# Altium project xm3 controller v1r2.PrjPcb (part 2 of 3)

## Sheet LAUNCHPAD.SchDoc: Controller
size 492 x 365 mm; OrgAddr3: USA; Page Create Date: March  8, 1995; OrgName: Wolfspeed; OrgAddr1: 535 W Research Center Blvd.; Page Number: 1; Page Size: A; Comment: DualBrandTitleBlock1; Page Count: 8; OrgAddr2: Fayetteville, AR, 72701; Page Name: LAUNCHPAD; RevCode: V1.2; DsnPath: C:\Users\cnew\Downloads\xm3 controller v1r2-2022-03-14T15-49\xm3 controller v1r2.dsn; SchematicName: SCHEMATIC1; PageName: LAUNCHPAD; PageSize: A; TopSchematic: True
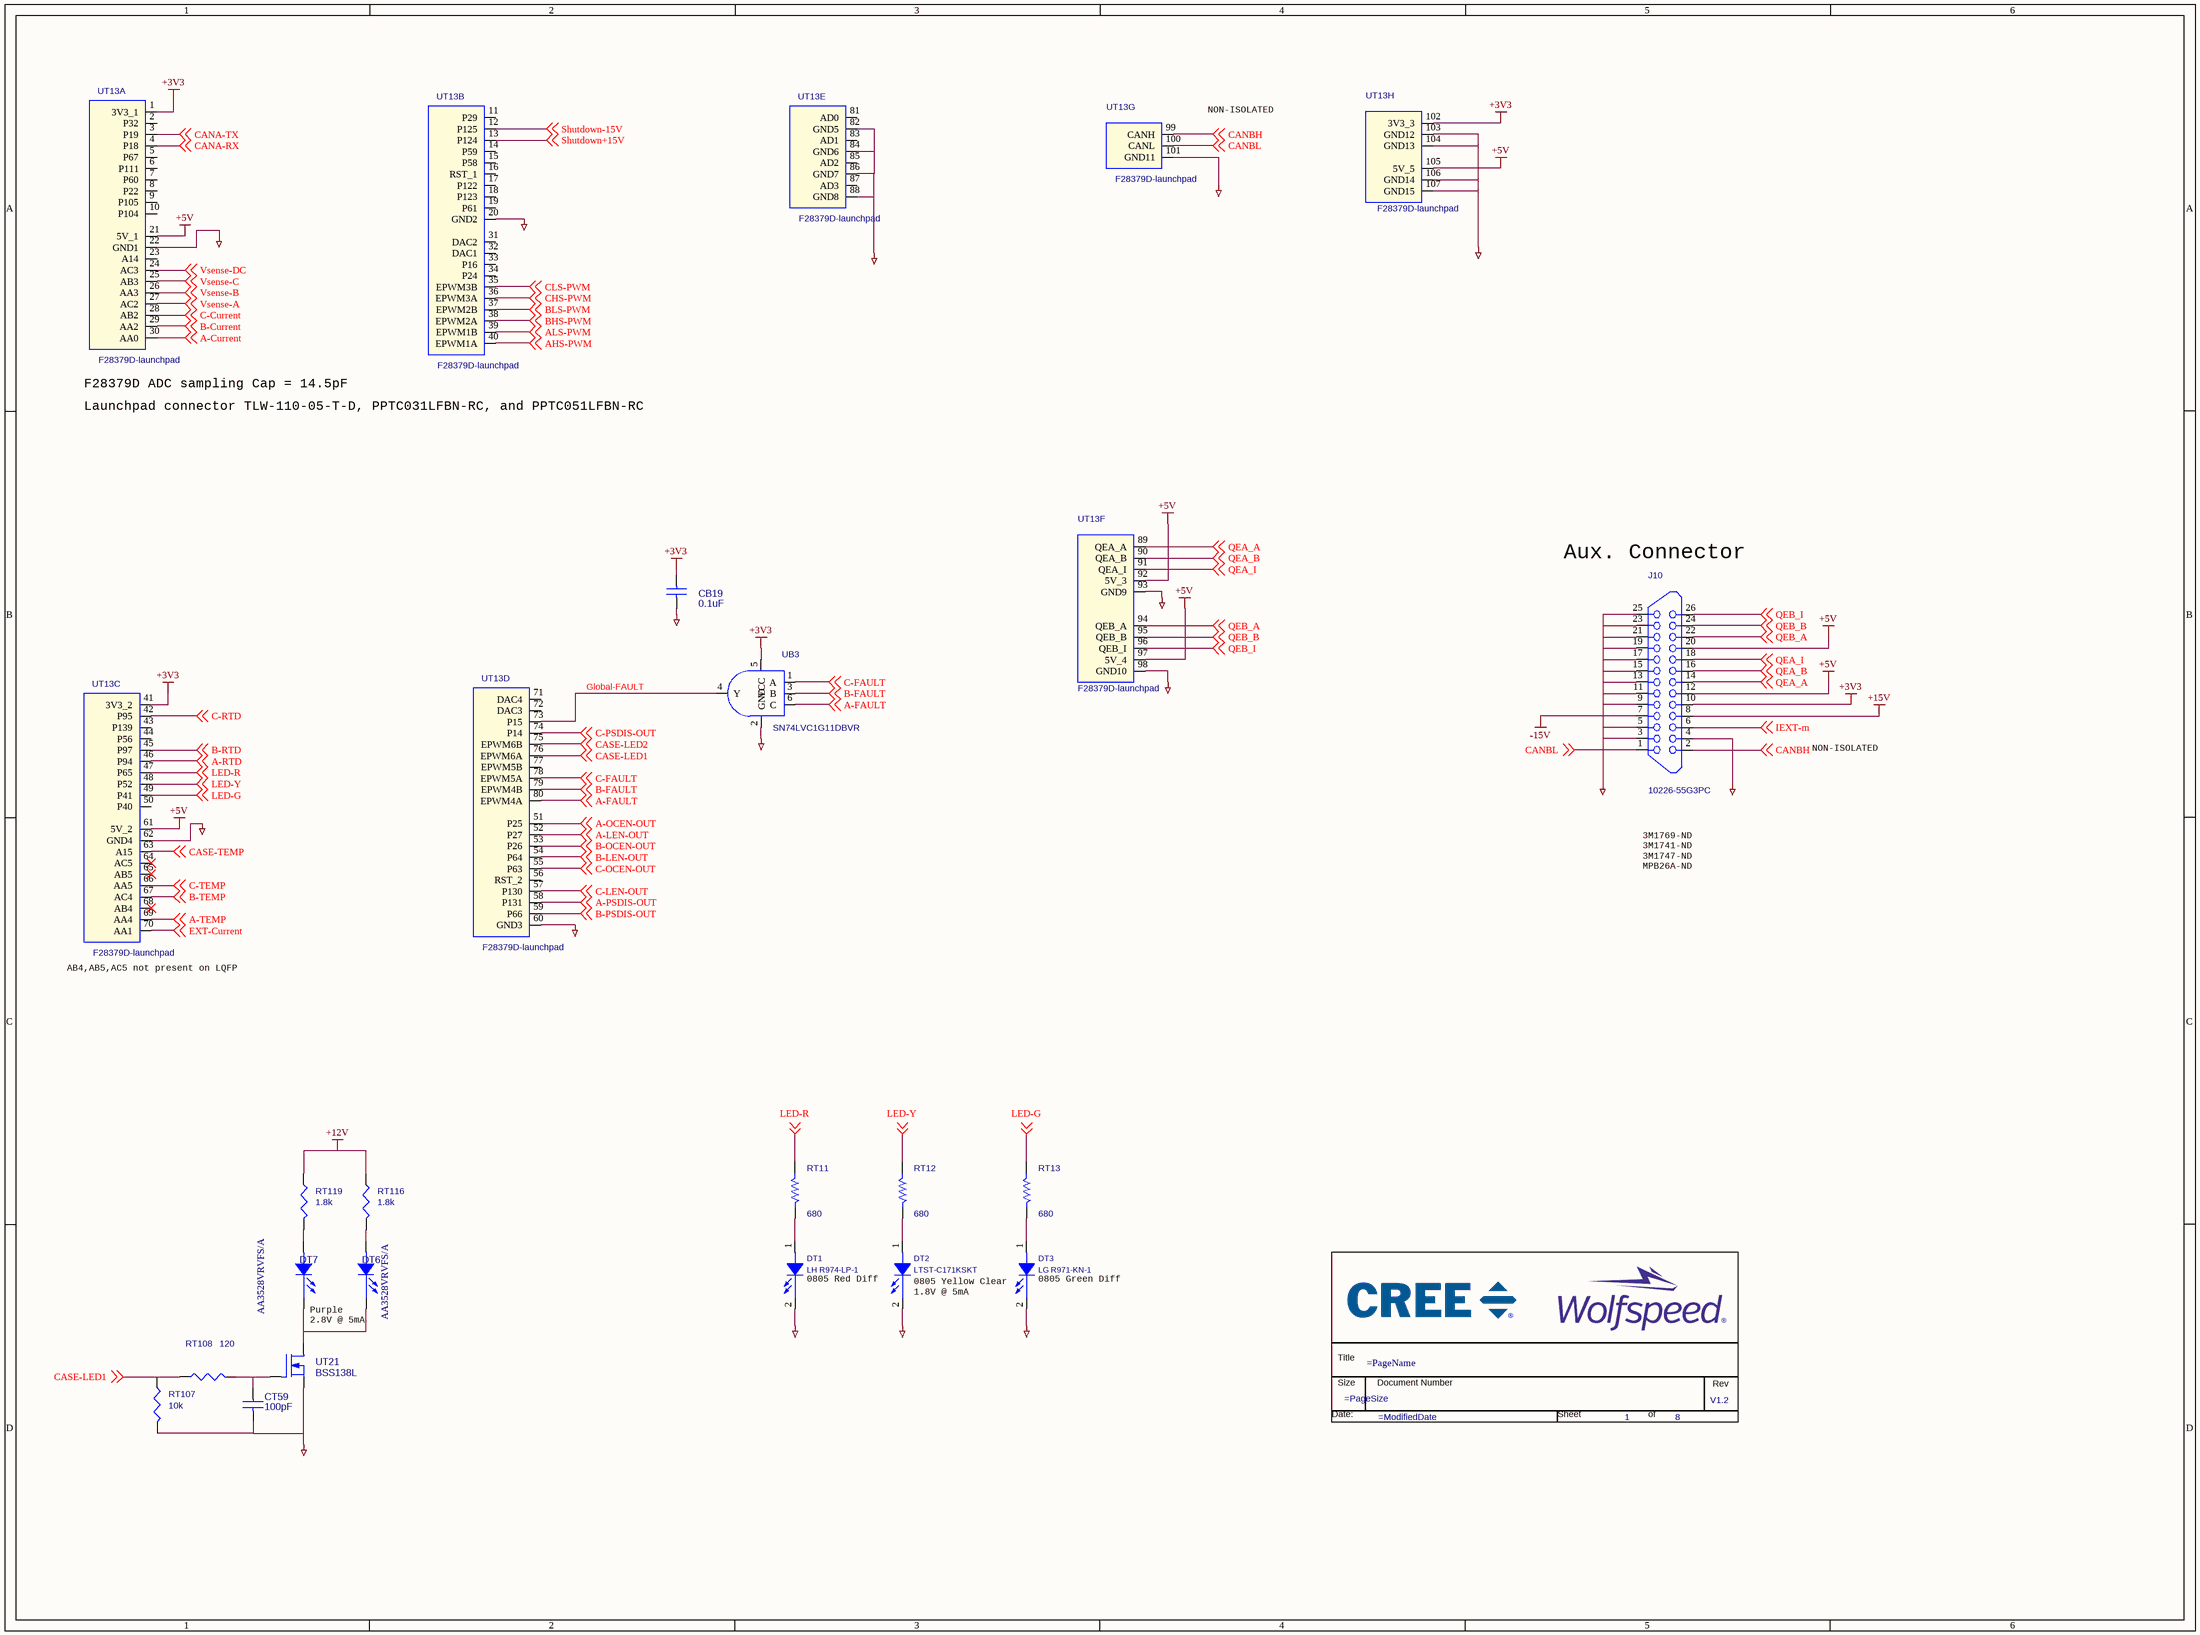
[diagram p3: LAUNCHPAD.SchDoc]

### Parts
(Parts that share a designator on the sheet are numbered #1, #2 ... from top to bottom, then left to right.)
*#4  Page Count: 8  Page Number: 1  RevCode: V1.2  (hidden comment: DualBrandTitleBlock1)  (graphical)
CB19  0.1uF  [CAPC1608X87N]
CT59  100pF  [CAPC1608X90N]
DT1  LH R974-LP-1  [D_0805]
DT2  LTST-C171KSKT  [D_0805]
DT3  LG R971-KN-1  [D_0805]
DT6  AA3528VRVFS/A  [D_1409]
DT7  AA3528VRVFS/A  [D_1409]
J10  10226-55G3PC  [MDR-26]
RT11  680  [RESC1608X55N]
RT12  680  [RESC1608X55N]
RT13  680  [RESC1608X55N]
RT107  10k  [RESC1608X65N]
RT108  120  [RESC1608X55N]
RT116  1.8k  [RESC2013X65N]
RT119  1.8k  [RESC2013X65N]
UB3  SN74LVC1G11DBVR  [SOT-23-6]
UT13  F28379D-launchpad  [F28379D-Launchpad-1]  (parts A,B,C,D,E,F,G,H of 8)
UT21  BSS138L  [SOT_23_3]

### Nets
0: CB19.2 CT59.2 DT1.2(C) DT2.2(C) DT3.2(C) J10.3 J10.4 J10.5 J10.9 J10.11 J10.13 J10.15 J10.17 J10.19 J10.21 J10.23 J10.25 RT107.2 UB3.2(GND) UT13.20(GND2) UT13.22(GND1) UT13.60(GND3) UT13.62(GND4) UT13.82(GND5) UT13.84(GND6) UT13.86(GND7) UT13.88(GND8) UT13.93(GND9) UT13.98(GND10) UT13.101(GND11) UT13.103(GND12) UT13.104(GND13) UT13.106(GND14) UT13.107(GND15) UT21.2(S)
+3V3: CB19.1 J10.10 UB3.5(VCC) UT13.1(3V3_1) UT13.41(3V3_2) UT13.102(3V3_3)
+5V: J10.12 J10.20 UT13.21(5V_1) UT13.61(5V_2) UT13.92(5V_3) UT13.97(5V_4) UT13.105(5V_5)
+12V: RT116.1 RT119.1
+15V: J10.8
-15V: J10.7
A-Current: UT13.30(AA0) ; off-sheet A-Current
A-FAULT: UB3.6(C) UT13.80(EPWM4A) ; off-sheet A-FAULT
A-LEN-OUT: UT13.52(P27) ; off-sheet A-LEN-OUT
A-OCEN-OUT: UT13.51(P25) ; off-sheet A-OCEN-OUT
A-PSDIS-OUT: UT13.58(P131) ; off-sheet A-PSDIS-OUT
A-RTD: UT13.46(P94) ; off-sheet A-RTD
A-TEMP: UT13.69(AA4) ; off-sheet A-TEMP
AHS-PWM: UT13.40(EPWM1A) ; off-sheet AHS-PWM
ALS-PWM: UT13.39(EPWM1B) ; off-sheet ALS-PWM
B-Current: UT13.29(AA2) ; off-sheet B-Current
B-FAULT: UB3.3(B) UT13.79(EPWM4B) ; off-sheet B-FAULT
B-LEN-OUT: UT13.54(P64) ; off-sheet B-LEN-OUT
B-OCEN-OUT: UT13.53(P26) ; off-sheet B-OCEN-OUT
B-PSDIS-OUT: UT13.59(P66) ; off-sheet B-PSDIS-OUT
B-RTD: UT13.45(P97) ; off-sheet B-RTD
B-TEMP: UT13.67(AC4) ; off-sheet B-TEMP
BHS-PWM: UT13.38(EPWM2A) ; off-sheet BHS-PWM
BLS-PWM: UT13.37(EPWM2B) ; off-sheet BLS-PWM
C-Current: UT13.28(AB2) ; off-sheet C-Current
C-FAULT: UB3.1(A) UT13.78(EPWM5A) ; off-sheet C-FAULT
C-LEN-OUT: UT13.57(P130) ; off-sheet C-LEN-OUT
C-OCEN-OUT: UT13.55(P63) ; off-sheet C-OCEN-OUT
C-PSDIS-OUT: UT13.74(P14) ; off-sheet C-PSDIS-OUT
C-RTD: UT13.42(P95) ; off-sheet C-RTD
C-TEMP: UT13.66(AA5) ; off-sheet C-TEMP
CANA-RX: UT13.4(P18) ; off-sheet CANA-RX
CANA-TX: UT13.3(P19) ; off-sheet CANA-TX
CANBH: J10.2 UT13.99(CANH) ; off-sheet CANBH
CANBL: J10.1 UT13.100(CANL) ; off-sheet CANBL
CASE-LED1: RT107.1 RT108.1 UT13.76(EPWM6A) ; off-sheet CASE-LED1
CASE-LED2: UT13.75(EPWM6B) ; off-sheet CASE-LED2
CASE-TEMP: UT13.63(A15) ; off-sheet CASE-TEMP
CHS-PWM: UT13.36(EPWM3A) ; off-sheet CHS-PWM
CLS-PWM: UT13.35(EPWM3B) ; off-sheet CLS-PWM
EXT-Current: UT13.70(AA1) ; off-sheet EXT-Current
Global-FAULT: UB3.4(Y) UT13.73(P15)
IEXT-m: J10.6 ; off-sheet IEXT-m
LED-G: RT13.1 UT13.49(P41) ; off-sheet LED-G
LED-R: RT11.1 UT13.47(P65) ; off-sheet LED-R
LED-Y: RT12.1 UT13.48(P52) ; off-sheet LED-Y
QEA_A: J10.14 UT13.89(QEA_A) ; off-sheet QEA_A
QEA_B: J10.16 UT13.90(QEA_B) ; off-sheet QEA_B
QEA_I: J10.18 UT13.91(QEA_I) ; off-sheet QEA_I
QEB_A: J10.22 UT13.94(QEB_A) ; off-sheet QEB_A
QEB_B: J10.24 UT13.95(QEB_B) ; off-sheet QEB_B
QEB_I: J10.26 UT13.96(QEB_I) ; off-sheet QEB_I
Shutdown+15V: UT13.13(P124) ; off-sheet Shutdown+15V
Shutdown-15V: UT13.12(P125) ; off-sheet Shutdown-15V
Vsense-A: UT13.27(AC2) ; off-sheet Vsense-A
Vsense-B: UT13.26(AA3) ; off-sheet Vsense-B
Vsense-C: UT13.25(AB3) ; off-sheet Vsense-C
Vsense-DC: UT13.24(AC3) ; off-sheet Vsense-DC
NetCT59_1: CT59.1 RT108.2 UT21.1(G)
NetDT1_1: DT1.1(A) RT11.2
NetDT2_1: DT2.1(A) RT12.2
NetDT3_1: DT3.1(A) RT13.2
NetDT6_1: DT6.1(ANODE) RT116.2
NetDT6_2: DT6.2(CATHODE) DT7.2(CATHODE) UT21.3(D)
NetDT7_1: DT7.1(ANODE) RT119.2

Not connected (* = marked no-connect by the designer): UT13 2(P32) 5(P67) 6(P111) 7(P60) 8(P22) 9(P105) 10(P104) 11(P29) 14(P59) 15(P58) 16(RST_1) 17(P122) 18(P123) 19(P61) 23(A14) 31(DAC2) 32(DAC1) 33(P16) 34(P24) 43(P139) 44(P56) 50(P40) 56(RST_2) 64(AC5)* 65(AB5)* 68(AB4)* 71(DAC4) 72(DAC3) 77(EPWM5B) 81(AD0) 83(AD1) 85(AD2) 87(AD3)

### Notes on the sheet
- NON-ISOLATED
- (near UT13) F28379D ADC sampling Cap = 14.5pF
- Launchpad connector TLW-110-05-T-D, PPTC031LFBN-RC, and PPTC051LFBN-RC
- Aux. Connector
- 3M1769-ND
  3M1741-ND
  3M1747-ND
  MPB26A-ND
- (near UT13) AB4,AB5,AC5 not present on LQFP
- Purple
  2.8V @ 5mA
- (near DT1) 0805 Red Diff
- 0805 Yellow Clear
  1.8V @ 5mA
- (near DT3) 0805 Green Diff

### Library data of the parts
*#4 = DualBrandTitleBlock1: OrgAddr3: USA; OrgAddr2: Fayetteville, AR, 72701; OrgAddr1: 535 W Research Center Blvd.; OrgName: Wolfspeed; Title: Controller
CB19 = CAP: CAP CER 0.1UF 25V X7R 0603; Part Reference: CB19; PART_NUMBER: TMP-847; Manufacturer: Kemet; Manufacturer PN: C0603C104K3RACTU; Company Part Status: New; Dielectric Type: Capacitors; Tolerance: 10%; CLASS: DISCRETE
CT59 = CAP: CAP CER 100PF 50V 5% NP0 0603; Part Reference: CT59; Manufacturer PN: CL10C101JB8NNNC; Manufacturer: Samsung Electro-Mechanics America, Inc; PART_NUMBER: TMP-455; Company Part Status: New; CLASS: DISCRETE; Temperature Coefficient: C0G, NP0; Dielectric Type: Capacitors
DT1 = LED_0: LED RED DIFFUSED 0805 SMD; Part Reference: DT1; Company Part Status: New; PART_NUMBER: TMP-917; Manufacturer: OSRAM Opto Semiconductors Inc.; Rated Voltage: 1.8V @ 20mA; CLASS: DISCRETE
DT2 = LED_0: LED YELLOW CLEAR 0805 SMD; Part Reference: DT2; Company Part Status: New; Manufacturer: Lite-On Inc.; PART_NUMBER: TMP-656; CLASS: DISCRETE
DT3 = LED_0: LED GREEN DIFFUSED 0805 SMD; Part Reference: DT3; Manufacturer: OSRAM Opto Semiconductors Inc.; PART_NUMBER: TMP-915; Company Part Status: New; CLASS: DISCRETE; Rated Voltage: 2.2V
DT6 = LED - Purple: Standard LEDs - SMD Violet Water Clear 250mcd 120 Deg; Manufacturer: Kingbright; Part Reference: DT6; PART_NUMBER: TMP-147; Company Part Status: Released; CLASS: DISCRETE
DT7 = LED - Purple: Standard LEDs - SMD Violet Water Clear 250mcd 120 Deg; Manufacturer: Kingbright; Part Reference: DT7; PART_NUMBER: TMP-147; Company Part Status: Released; CLASS: DISCRETE
J10 = CONN CENT RCPT 26: CONN RCPT 26POS R/A SOLDER; Part Reference: J10; Manufacturer: 3M; Company Part Status: New; CLASS: IO
RT11 = RES_Dup1: RES SMD 680 OHM 1% 1/10W 0603; Part Reference: RT11; Company Part Status: New; Manufacturer: Yageo; Manufacturer PN: RC0603FR-07680RL; Temperature Coefficient: 100ppm/C; Rated Power: 0.1W, 1/10W; CLASS: DISCRETE
RT12 = RES_Dup1: RES SMD 680 OHM 1% 1/10W 0603; Part Reference: RT12; Manufacturer PN: RC0603FR-07680RL; Manufacturer: Yageo; Company Part Status: New; CLASS: DISCRETE; Rated Power: 0.1W, 1/10W; Temperature Coefficient: 100ppm/C
RT13 = RES_Dup1: RES SMD 680 OHM 1% 1/10W 0603; Part Reference: RT13; Manufacturer PN: RC0603FR-07680RL; Manufacturer: Yageo; Company Part Status: New; CLASS: DISCRETE; Rated Power: 0.1W, 1/10W; Temperature Coefficient: 100ppm/C
RT107 = R: RES SMD 10K OHM 1% 1/10W 0603; Part Reference: RT107; PART_NUMBER: TMP-380; Manufacturer: Rohm Semiconductor; Manufacturer PN: MCR03ERTF1002; Company Part Status: New; Temperature Coefficient: 100ppm/C; Rated Power: 0.1W, 1/10W; CLASS: DISCRETE
RT108 = R: RES SMD 120 OHM 5% 1/10W 0603; Part Reference: RT108; Manufacturer PN: RC0603JR-07120RL; Manufacturer: Yageo; PART_NUMBER: TMP-619; Company Part Status: New; CLASS: DISCRETE; Rated Power: 0.1W, 1/10W; Temperature Coefficient: 100ppm/C
RT116 = R: RES 1.8K OHM 1/8W 1% 0805 SMD; Part Reference: RT116; Manufacturer PN: KTR10EZPF1801; Manufacturer: Rohm Semiconductor; PART_NUMBER: TMP-277; CLASS: DISCRETE; Rated Power: 0.125W, 1/8W; Temperature Coefficient: 100ppm/C
RT119 = R: RES 1.8K OHM 1/8W 1% 0805 SMD; Part Reference: RT119; PART_NUMBER: TMP-277; Manufacturer: Rohm Semiconductor; Manufacturer PN: KTR10EZPF1801; Temperature Coefficient: 100ppm/C; Rated Power: 0.125W, 1/8W; CLASS: DISCRETE
UB3 = AND3_1X_6PIN: IC GATE AND 1CH 3-INP SOT23-6; Part Reference: UB3; Manufacturer: Texas Instruments; Company Part Status: New; Supply Voltage: 1.65 V - 5.5 V; PCB Footprint: SOT_23_6
UT13 = F28379D-launchpad: Part Reference: UT13
UT21 = MOSFET_N_GSD: MOSFET N-CH 50V 0.2A SOT-23; Part Reference: UT21; Manufacturer: ON Semiconductor; Company Part Status: Released; CLASS: DISCRETE; Polarity: N-Channel; Rated Power: 350mW

## Sheet Power Supply.SchDoc: Controller
size 492 x 365 mm; OrgAddr3: USA; Page Create Date: March  8, 1995; OrgName: Wolfspeed; OrgAddr1: 535 W Research Center Blvd.; Page Number: 6; Page Size: A; Comment: DualBrandTitleBlock1; Page Count: 8; OrgAddr2: Fayetteville, AR, 72701; Page Name: Power Supply; RevCode: V1.2; DsnPath: C:\Users\cnew\Downloads\xm3 controller v1r2-2022-03-14T15-49\xm3 controller v1r2.dsn; SchematicName: SCHEMATIC1; PageName: Power Supply; PageSize: A; TopSchematic: True
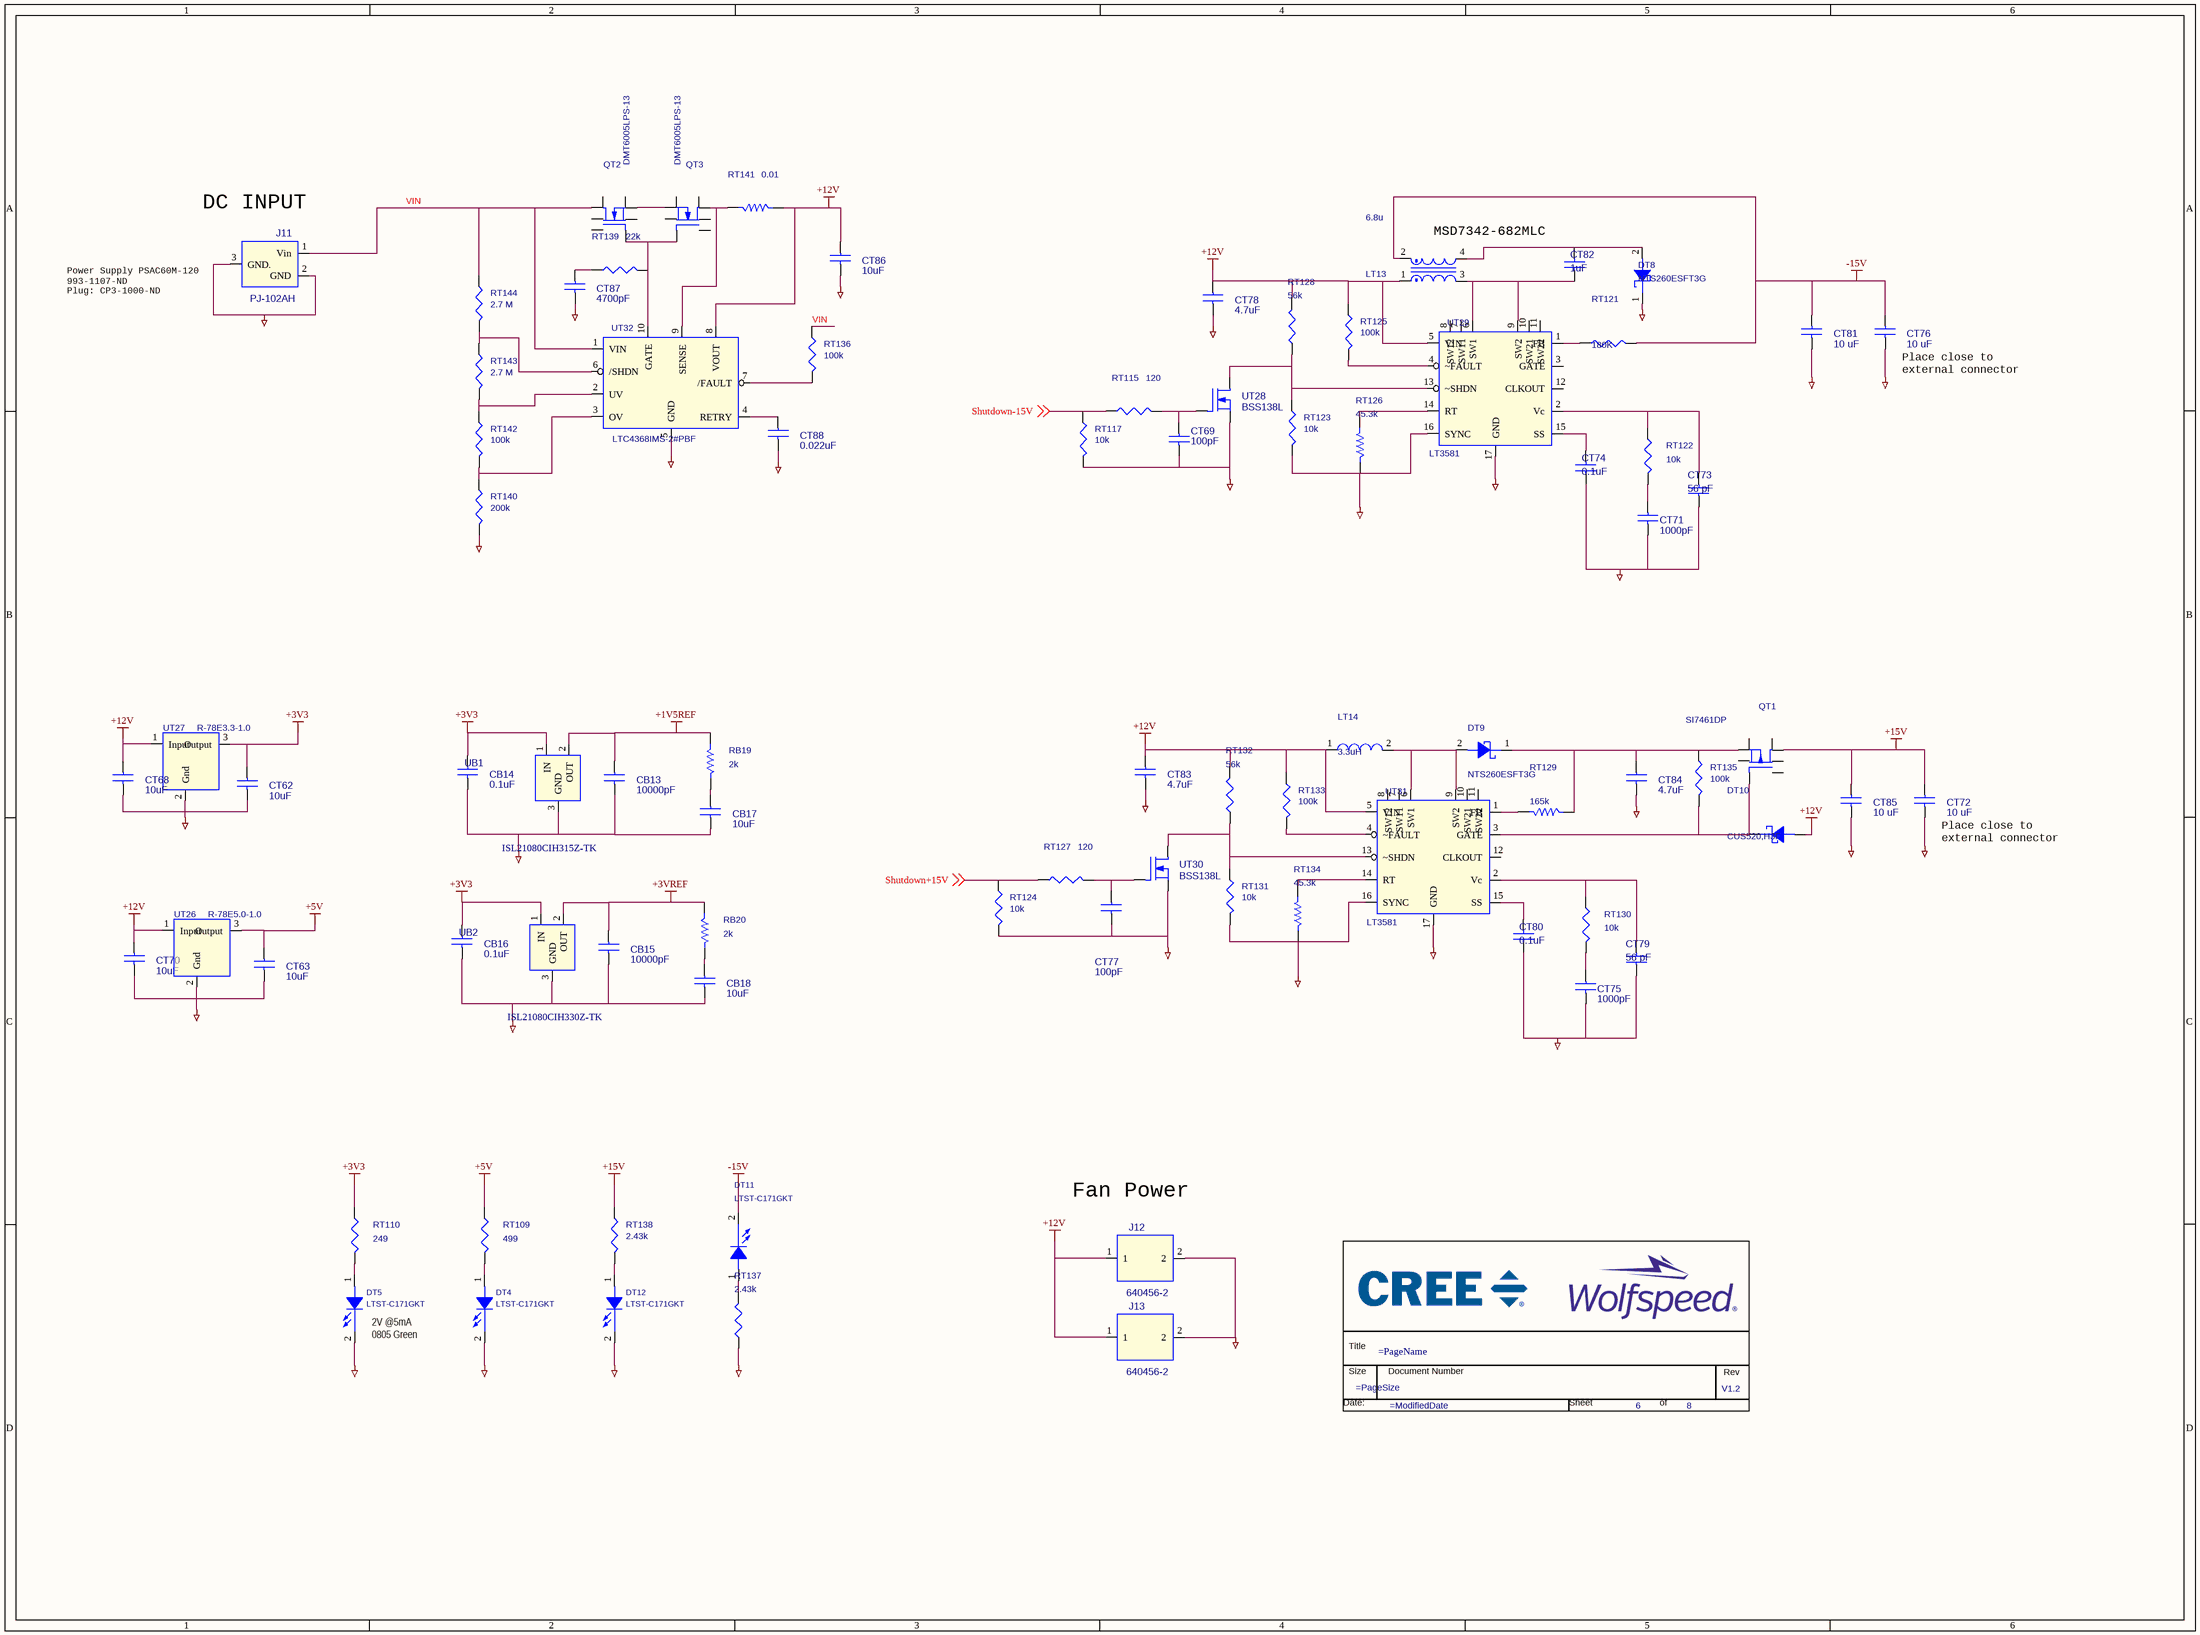
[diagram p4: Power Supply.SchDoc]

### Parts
(Parts that share a designator on the sheet are numbered #1, #2 ... from top to bottom, then left to right.)
*#5  Page Count: 8  Page Number: 6  RevCode: V1.2  (hidden comment: DualBrandTitleBlock1)  (graphical)
CB13  10000pF  [CAPC1608X90N]
CB14  0.1uF  [CAPC1608X87N]
CB15  10000pF  [CAPC1608X90N]
CB16  0.1uF  [CAPC1608X87N]
CB17  10uF  [CAPC1608X90N]
CB18  10uF  [CAPC1608X90N]
CT62  10uF  [CAPC2012X135N]
CT63  10uF  [CAPC2012X135N]
CT68  10uF  [CAPC2012X135N]
CT69  100pF  [CAPC1608X90N]
CT70  10uF  [CAPC2012X135N]
CT71  1000pF  [CAPC1608X90N]
CT72  10 uF  [CAPC3216X180N]
CT73  56 pF  [CAPC1608X90N]
CT74  0.1uF  [CAPC1608X90N]
CT75  1000pF  [CAPC1608X90N]
CT76  10 uF  [CAPC3216X180N]
CT77  100pF  [CAPC1608X90N]
CT78  4.7uF  [CAPc3216X180N]
CT79  56 pF  [CAPC1608X90N]
CT80  0.1uF  [CAPC1608X90N]
CT81  10 uF  [CAPC3216X180N]
CT82  1uF  [CAPC2012X70N]
CT83  4.7uF  [CAPc3216X180N]
CT84  4.7uF  [CAPc3216X180N]
CT85  10 uF  [CAPC3216X180N]
CT86  10uF  [CAPC2012X135N]
CT87  4700pF  [CAPC1608X90N]
CT88  0.022uF  [CAPC2012X70N]
DT4  LTST-C171GKT  [D_0805]
DT5  LTST-C171GKT  [D_0805]
DT8  NTS260ESFT3G  [SOD-123F-AC]
DT9  NTS260ESFT3G  [SOD-123F-AC]
DT10  CUS520,H3F  [SOD-323-AC]
DT11  LTST-C171GKT  [D_0805]
DT12  LTST-C171GKT  [D_0805]
J11  PJ-102AH  [powerjack]
J12  640456-2  [CON_1x2_vert_lock]
J13  640456-2  [CON_1x2_vert_lock]
LT13  6.8u  [SRF1260]
LT14  3.3uH  [IND-5040]
QT1  SI7461DP  [POWER-SO8]
QT2  DMT6005LPS-13  [POWER-SO8]
QT3  DMT6005LPS-13  [POWER-SO8]
RB19  2k  [RESC1608X55N]
RB20  2k  [RESC1608X55N]
RT109  499  [RESC2012X60N]
RT110  249  [RESC2012X60N]
RT115  120  [RESC1608X55N]
RT117  10k  [RESC1608X65N]
RT121  180K  [RESC1608X55N]
RT122  10k  [RESC1608X65N]
RT123  10k  [RESC1608X65N]
RT124  10k  [RESC1608X65N]
RT125  100k  [RESC1608X55N]
RT126  45.3k  [RESC1608X55N]
RT127  120  [RESC1608X55N]
RT128  56k  [RESC1608X55N]
RT129  165k  [RESC1608X55N]
RT130  10k  [RESC1608X65N]
RT131  10k  [RESC1608X65N]
RT132  56k  [RESC1608X55N]
RT133  100k  [RESC1608X55N]
RT134  45.3k  [RESC1608X55N]
RT135  100k  [RESC1608X55N]
RT136  100k  [RESC1608X55N]
RT137  2.43k  [RESC2012X60N]
RT138  2.43k  [RESC2012X60N]
RT139  22k  [RESC1608X55N]
RT140  200k  [RESC1608X55N]
RT141  0.01  [RESC6432X70N]
RT142  100k  [RESC1608X55N]
RT143  2.7 M  [RESC1608X55N]
RT144  2.7 M  [RESC1608X55N]
UB1  ISL21080CIH315Z-TK  [SOT_23_3]
UB2  ISL21080CIH330Z-TK  [SOT_23_3]
UT26  R-78E5.0-1.0  [TO_220_3]
UT27  R-78E3.3-1.0  [TO_220_3]
UT28  BSS138L  [SOT_23_3]
UT29  LT3581  [MSOP-16-EP]
UT30  BSS138L  [SOT_23_3]
UT31  LT3581  [MSOP-16-EP]
UT32  LTC4368IMS-2#PBF  [MSOP_10]

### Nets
0: CB13.2 CB14.2 CB15.2 CB16.2 CB17.2 CB18.2 CT62.2 CT63.2 CT68.2 CT69.2 CT70.2 CT71.2 CT72.2 CT73.1 CT74.1 CT75.2 CT76.2 CT77.2 CT78.2 CT79.1 CT80.1 CT81.2 CT83.2 CT84.2 CT85.2 CT86.2 CT87.2 CT88.2 DT4.2(C) DT5.2(C) DT8.1(C) DT12.2(C) J11.2(GND) J11.3(GND.) J12.2 J13.2 RT117.2 RT123.2 RT124.2 RT126.1 RT131.2 RT134.1 RT137.1 RT140.2 UB1.3(GND) UB2.3(GND) UT26.2(Gnd) UT27.2(Gnd) UT28.2(S) UT29.16(SYNC) UT29.17(GND) UT30.2(S) UT31.16(SYNC) UT31.17(GND) UT32.5(GND)
+1V5REF: CB13.1 RB19.1 UB1.2(OUT)
+3V3: CB14.1 CB16.1 CT62.1 RT110.1 UB1.1(IN) UB2.1(IN) UT27.3(Output)
+3VREF: CB15.1 RB20.1 UB2.2(OUT)
+5V: CT63.1 RT109.1 UT26.3(Output)
+12V: CT68.1 CT70.1 CT78.1 CT83.1 CT86.1 DT10.A(ANODE) J12.1 J13.1 LT13.1 LT14.1 RT125.1 RT128.2 RT132.2 RT133.1 RT141.2 UT26.1(Input) UT27.1(Input) UT29.5(VIN) UT31.5(VIN) UT32.8(VOUT)
+15V: CT72.1 CT85.1 QT1.5(D) RT138.1
-15V: CT76.1 CT81.1 DT11.2(C) LT13.2 RT121.2
Shutdown+15V: RT124.1 RT127.1 ; off-sheet Shutdown+15V
Shutdown-15V: RT115.1 RT117.1 ; off-sheet Shutdown-15V
VIN: J11.1(Vin) QT2.5(D) RT136.1 RT144.1 UT32.1(VIN)
NetCB17_1: CB17.1 RB19.2
NetCB18_1: CB18.1 RB20.2
NetCT69_1: CT69.1 RT115.2 UT28.1(G)
NetCT71_1: CT71.1 RT122.2
NetCT73_2: CT73.2 RT122.1 UT29.2(Vc)
NetCT74_2: CT74.2 UT29.15(SS)
NetCT75_1: CT75.1 RT130.2
NetCT77_1: CT77.1 RT127.2 UT30.1(G)
NetCT79_2: CT79.2 RT130.1 UT31.2(Vc)
NetCT80_2: CT80.2 UT31.15(SS)
NetCT82_1: CT82.1 LT13.3 UT29.6(SW1) UT29.9(SW2)
NetCT82_2: CT82.2 DT8.2(A) LT13.4
NetCT84_1: CT84.1 DT9.1(C) QT1.1(S) RT129.2 RT135.1
NetCT87_1: CT87.1 RT139.1
NetCT88_1: CT88.1 UT32.4(RETRY)
NetDT4_1: DT4.1(A) RT109.2
NetDT5_1: DT5.1(A) RT110.2
NetDT9_2: DT9.2(A) LT14.2 UT31.6(SW1) UT31.9(SW2)
NetDT10_C: DT10.C(CATHODE) QT1.4(G) RT135.2 UT31.3(GATE)
NetDT11_1: DT11.1(A) RT137.2
NetDT12_1: DT12.1(A) RT138.2
NetQT2_1: QT2.1(S) QT3.1(S)
NetQT2_4: QT2.4(G) QT3.4(G) RT139.2 UT32.10(GATE)
NetQT3_5: QT3.5(D) RT141.1 UT32.9(SENSE)
NetRT121_1: RT121.1 UT29.1(FB)
NetRT123_1: RT123.1 RT128.1 UT28.3(D) UT29.13(~SHDN)
NetRT125_2: RT125.2 UT29.4(~FAULT)
NetRT126_2: RT126.2 UT29.14(RT)
NetRT129_1: RT129.1 UT31.1(FB)
NetRT131_1: RT131.1 RT132.1 UT30.3(D) UT31.13(~SHDN)
NetRT133_2: RT133.2 UT31.4(~FAULT)
NetRT134_2: RT134.2 UT31.14(RT)
NetRT136_2: RT136.2 UT32.7(/FAULT)
NetRT140_1: RT140.1 RT142.2 UT32.3(OV)
NetRT142_1: RT142.1 RT143.2 UT32.2(UV)
NetRT143_1: RT143.1 RT144.2 UT32.6(/SHDN)

Not connected (* = marked no-connect by the designer): QT1 2(S1) 3(S2) 6(D1) 7(D2) 8(D3); QT2 2(S1) 3(S2) 6(D1) 7(D2) 8(D3); QT3 2(S1) 3(S2) 6(D1) 7(D2) 8(D3); UT29 3(GATE) 7(SW11) 8(SW12) 10(SW21) 11(SW22) 12(CLKOUT); UT31 7(SW11) 8(SW12) 10(SW21) 11(SW22) 12(CLKOUT)

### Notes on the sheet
- (near J11) DC INPUT
- (near LT13) MSD7342-682MLC
- (near J11) Power Supply PSAC60M-120
  993-1107-ND
- Plug: CP3-1000-ND
- (near CT76) Place close to
  external connector
- (near CT72) Place close to
  external connector
- Fan Power
- (near DT5) 2V @5mA
  0805 Green

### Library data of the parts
*#5 = DualBrandTitleBlock1: as *#4 on sheet LAUNCHPAD
CB13 = CAP: CAP CER 10000PF 25V 10% X7R 0603; Part Reference: CB13; PART_NUMBER: TMP-566; Manufacturer: Samsung Electro-Mechanics America, Inc.; Manufacturer PN: CL10B103KA8NNNC; Company Part Status: New; Dielectric Type: Capacitors; CLASS: DISCRETE
CB14 = CAP: CAP CER 0.1UF 25V X7R 0603; Part Reference: CB14; PART_NUMBER: TMP-847; Manufacturer: Kemet; Manufacturer PN: C0603C104K3RACTU; Company Part Status: New; Dielectric Type: Capacitors; Tolerance: 10%; CLASS: DISCRETE
CB15 = CAP: CAP CER 10000PF 25V 10% X7R 0603; Part Reference: CB15; PART_NUMBER: TMP-566; Manufacturer: Samsung Electro-Mechanics America, Inc.; Manufacturer PN: CL10B103KA8NNNC; Company Part Status: New; Dielectric Type: Capacitors; CLASS: DISCRETE
CB16 = CAP: CAP CER 0.1UF 25V X7R 0603; Part Reference: CB16; PART_NUMBER: TMP-847; Manufacturer: Kemet; Manufacturer PN: C0603C104K3RACTU; Company Part Status: New; Dielectric Type: Capacitors; Tolerance: 10%; CLASS: DISCRETE
CB17 = CAP: CAP CER 10UF 6.3V X7R 0603; Part Reference: CB17; Manufacturer: Samsung Electro-Mechanics America, Inc.; Manufacturer PN: CL10B106MQ8NRNC; Company Part Status: New; Dielectric Type: Capacitors; Tolerance: 20%; CLASS: DISCRETE
CB18 = CAP: CAP CER 10UF 6.3V X7R 0603; Part Reference: CB18; Manufacturer: Samsung Electro-Mechanics America, Inc.; Manufacturer PN: CL10B106MQ8NRNC; Company Part Status: New; Dielectric Type: Capacitors; Tolerance: 20%; CLASS: DISCRETE
CT62 = CAP: CAP CER 10UF 25V X7S 0805; Part Reference: CT62; Manufacturer: Murata Electronics North America; Manufacturer PN: GRM21BC71E106KE11L; Company Part Status: New; Dielectric Type: Capacitors; Tolerance: 10%; CLASS: DISCRETE
CT63 = CAP: CAP CER 10UF 25V X7S 0805; Part Reference: CT63; Manufacturer: Murata Electronics North America; Manufacturer PN: GRM21BC71E106KE11L; Company Part Status: New; Dielectric Type: Capacitors; Tolerance: 10%; CLASS: DISCRETE
CT68 = CAP: CAP CER 10UF 25V X7S 0805; Part Reference: CT68; Manufacturer: Murata Electronics North America; Manufacturer PN: GRM21BC71E106KE11L; Company Part Status: New; Dielectric Type: Capacitors; Tolerance: 10%; CLASS: DISCRETE
CT69 = CAP: CAP CER 100PF 50V 5% NP0 0603; Part Reference: CT69; PART_NUMBER: TMP-455; Manufacturer: Samsung Electro-Mechanics America, Inc; Manufacturer PN: CL10C101JB8NNNC; Company Part Status: New; Dielectric Type: Capacitors; Temperature Coefficient: C0G, NP0; CLASS: DISCRETE
CT70 = CAP: CAP CER 10UF 25V X7S 0805; Part Reference: CT70; Manufacturer: Murata Electronics North America; Manufacturer PN: GRM21BC71E106KE11L; Company Part Status: New; Dielectric Type: Capacitors; Tolerance: 10%; CLASS: DISCRETE
CT71 = CAP: CAP CER 1000PF 50V X7R 0603; Part Reference: CT71; PART_NUMBER: TMP-887; Manufacturer: TDK Corporation; Manufacturer PN: CGA3E2X7R1H102K080AA; Dielectric Type: Capacitors; Tolerance: 10%; CLASS: DISCRETE
CT72 = CAP: CAP CER 10UF 25V X7R 1206; Part Reference: CT72; Manufacturer PN: CL31B106KAHNNNE; Manufacturer: Samsung Electro-Mechanics; Company Part Status: Released; CLASS: DISCRETE; Tolerance: 10%; Dielectric Type: Capacitors
CT73 = CAP: CAP CER 56PF 50V C0G/NP0 0603; Part Reference: CT73; Manufacturer: Samsung Electro-Mechanics; Manufacturer PN: CL10C560JB8NNNC; Company Part Status: Released; Dielectric Type: Capacitors; Temperature Coefficient: C0G, NP0; Tolerance: 5%; CLASS: DISCRETE
CT74 = CAP: CAP CER 0.1UF 50V X7R 0603; Part Reference: CT74; Manufacturer PN: CC0603KRX7R9BB104; Manufacturer: Yageo; Company Part Status: Released; CLASS: DISCRETE; Tolerance: 10%; Dielectric Type: Capacitors
CT75 = CAP: CAP CER 1000PF 50V X7R 0603; Part Reference: CT75; PART_NUMBER: TMP-887; Manufacturer: TDK Corporation; Manufacturer PN: CGA3E2X7R1H102K080AA; Dielectric Type: Capacitors; Tolerance: 10%; CLASS: DISCRETE
CT76 = CAP: CAP CER 10UF 25V X7R 1206; Part Reference: CT76; Manufacturer: Samsung Electro-Mechanics; Manufacturer PN: CL31B106KAHNNNE; Company Part Status: Released; Dielectric Type: Capacitors; Tolerance: 10%; CLASS: DISCRETE
CT77 = CAP: CAP CER 100PF 50V 5% NP0 0603; Part Reference: CT77; PART_NUMBER: TMP-455; Manufacturer: Samsung Electro-Mechanics America, Inc; Manufacturer PN: CL10C101JB8NNNC; Company Part Status: New; Dielectric Type: Capacitors; Temperature Coefficient: C0G, NP0; CLASS: DISCRETE
CT78 = CAP: CAP CER 4.7UF 50V 10% X7R 1206; Part Reference: CT78; PART_NUMBER: TMP-119; Manufacturer: Taiyo Yuden; Manufacturer PN: UMK316AB7475KL-T; Dielectric Type: Ceramic; CLASS: DISCRETE
CT79 = CAP: CAP CER 56PF 50V C0G/NP0 0603; Part Reference: CT79; Manufacturer: Samsung Electro-Mechanics; Manufacturer PN: CL10C560JB8NNNC; Company Part Status: Released; Dielectric Type: Capacitors; Temperature Coefficient: C0G, NP0; Tolerance: 5%; CLASS: DISCRETE
CT80 = CAP: CAP CER 0.1UF 50V X7R 0603; Part Reference: CT80; Manufacturer PN: CC0603KRX7R9BB104; Manufacturer: Yageo; Company Part Status: Released; CLASS: DISCRETE; Tolerance: 10%; Dielectric Type: Capacitors
CT81 = CAP: CAP CER 10UF 25V X7R 1206; Part Reference: CT81; Manufacturer: Samsung Electro-Mechanics; Manufacturer PN: CL31B106KAHNNNE; Company Part Status: Released; Dielectric Type: Capacitors; Tolerance: 10%; CLASS: DISCRETE
CT82 = CAP: CAP CER 1UF 50V 10% X7R 0805; Part Reference: CT82; PART_NUMBER: TMP-453; Manufacturer: Samsung Electro-Mechanics America, Inc; Manufacturer PN: CL21B105KBFNNNE; Company Part Status: New; Dielectric Type: Capacitors; CLASS: DISCRETE
CT83 = CAP: CAP CER 4.7UF 50V 10% X7R 1206; Part Reference: CT83; PART_NUMBER: TMP-119; Manufacturer: Taiyo Yuden; Manufacturer PN: UMK316AB7475KL-T; Dielectric Type: Ceramic; CLASS: DISCRETE
CT84 = CAP: CAP CER 4.7UF 50V 10% X7R 1206; Part Reference: CT84; Manufacturer PN: UMK316AB7475KL-T; Manufacturer: Taiyo Yuden; PART_NUMBER: TMP-119; CLASS: DISCRETE; Dielectric Type: Ceramic
CT85 = CAP: CAP CER 10UF 25V X7R 1206; Part Reference: CT85; Manufacturer PN: CL31B106KAHNNNE; Manufacturer: Samsung Electro-Mechanics; Company Part Status: Released; CLASS: DISCRETE; Tolerance: 10%; Dielectric Type: Capacitors
CT86 = CAP: CAP CER 10UF 25V X7S 0805; Part Reference: CT86; Manufacturer: Murata Electronics North America; Manufacturer PN: GRM21BC71E106KE11L; Company Part Status: New; Dielectric Type: Capacitors; Tolerance: 10%; CLASS: DISCRETE
CT87 = CAP: CAP CER 4700PF 25V X7R 0603; Part Reference: CT87; PART_NUMBER: TMP-889; Manufacturer: Murata Electronics North America; Manufacturer PN: GCM188R71E472KA37D; Dielectric Type: Capacitors; Tolerance: 10%; CLASS: DISCRETE
CT88 = CAP: CAP CER 0.022UF 50V X7R 0805; Part Reference: CT88; Manufacturer PN: CC0805KRX7R9BB223; Manufacturer: Yageo; PART_NUMBER: TMP-667; Company Part Status: New; CLASS: DISCRETE; Tolerance: 10%; Dielectric Type: Ceramic
DT4 = LED_0: LED GREEN CLEAR 0805 SMD; Part Reference: DT4; Manufacturer: Lite-On Inc.; Company Part Status: Released; CLASS: DISCRETE
DT5 = LED_0: LED GREEN CLEAR 0805 SMD; Part Reference: DT5; Manufacturer: Lite-On Inc.; Company Part Status: Released; CLASS: DISCRETE
DT8 = DIODE_SCHOTTKY_0: DIODE SCHOTTKY 60V 2A SOD123FL; Part Reference: DT8; Manufacturer: ON Semiconductor; Company Part Status: New; CLASS: DISCRETE
DT9 = DIODE_SCHOTTKY_0: DIODE SCHOTTKY 60V 2A SOD123FL; Part Reference: DT9; Manufacturer: ON Semiconductor; Company Part Status: New; CLASS: DISCRETE
DT10 = DIODE_SCHOTTKY_C2_A1_0: DIODE SCHOTTKY 30V 200MA; Part Reference: DT10; PART_NUMBER: TMP-880; Manufacturer: Toshiba Semiconductor and Storage; Company Part Status: Released; Rated Voltage: 280mV @ 10mA; CLASS: DISCRETE
DT11 = LED_0: LED GREEN CLEAR 0805 SMD; Part Reference: DT11; Manufacturer: Lite-On Inc.; Company Part Status: Released; CLASS: DISCRETE
DT12 = LED_0: LED GREEN CLEAR 0805 SMD; Part Reference: DT12; Manufacturer: Lite-On Inc.; Company Part Status: Released; CLASS: DISCRETE
J11 = power_jack: CONN PWR JACK 2X5.5MM SOLDER; Part Reference: J11; Manufacturer: CUI Inc.; Company Part Status: New; CLASS: IO; PCB Footprint: powerjack-PJ102AH
J12 = 1x2 100mil: CONN HEADER VERT 2POS .100 TIN; Part Reference: J12; PART_NUMBER: TMP-943; Manufacturer: TE Connectivity AMP Connectors; Company Part Status: New; CLASS: IO
J13 = 1x2 100mil: CONN HEADER VERT 2POS .100 TIN; Part Reference: J13; Manufacturer: TE Connectivity AMP Connectors; PART_NUMBER: TMP-943; Company Part Status: New; CLASS: IO
LT13 = Coupled_Inductor: Manufacturer: Bourns; Part Number: MSD7342-682MLC; Part Reference: LT13; PCB Footprint: IND-MSD7342
LT14 = IND: FIXED IND 3.3UH 3.3A 27 MOHM SMD; Part Reference: LT14; Company Part Status: New; Manufacturer PN: NRS5040T3R3NMGJ; Manufacturer: Taiyo Yuden; CLASS: DISCRETE; Tolerance: 30%
QT1 = MOSFET_P_PSO8: MOSFET P-CH 60V 8.6A PPAK SO-8; Part Reference: QT1; Manufacturer PN: SI7461DP-T1-E3; Manufacturer: Vishay Siliconix; Company Part Status: New; PACK_SHORT: (S,S1,S2),(D,D1,D2,D3); CLASS: DISCRETE; Polarity: P-Channel; Rated Power: 1.9W (Ta)
QT2 = MOSFET_N_PSO8: MOSFET N-CHA 60V 17.9A POWERDI; Part Reference: QT2; Manufacturer: Diodes Incorporated; Company Part Status: New; PACK_SHORT: (S,S1,S2),(D,D1,D2,D3); Rated Power: 2.6 W; Polarity: N-Channel; CLASS: DISCRETE
QT3 = MOSFET_N_PSO8: MOSFET N-CHA 60V 17.9A POWERDI; Part Reference: QT3; Manufacturer: Diodes Incorporated; Company Part Status: New; PACK_SHORT: (S,S1,S2),(D,D1,D2,D3); Rated Power: 2.6 W; Polarity: N-Channel; CLASS: DISCRETE
RB19 = RES_Dup1: RES SMD 2K OHM 1% 1/10W 0603; Part Reference: RB19; Manufacturer PN: RC0603FR-072KL; Manufacturer: Yageo; Company Part Status: New; CLASS: DISCRETE; Rated Power: 0.1W, 1/10W; Temperature Coefficient: 100ppm/C
RB20 = RES_Dup1: RES SMD 2K OHM 1% 1/10W 0603; Part Reference: RB20; Manufacturer PN: RC0603FR-072KL; Manufacturer: Yageo; Company Part Status: New; CLASS: DISCRETE; Rated Power: 0.1W, 1/10W; Temperature Coefficient: 100ppm/C
RT109 = R: RES SMD 499 OHM 1% 1/8W 0805; Part Reference: RT109; PART_NUMBER: TMP-897; Manufacturer: Rohm Semiconductor; Manufacturer PN: MCR10ERTF4990; Company Part Status: New; Temperature Coefficient: 100ppm/C; Rated Power: 0.125W, 1/8W; CLASS: DISCRETE
RT110 = R: RES SMD 249 OHM 1% 1/8W 0805; Part Reference: RT110; PART_NUMBER: TMP-488; Manufacturer: Rohm Semiconductor; Manufacturer PN: MCR10ERTF2490; Company Part Status: New; Temperature Coefficient: 100ppm/C; Rated Power: 0.125W, 1/8W; CLASS: DISCRETE
RT115 = R: RES SMD 120 OHM 5% 1/10W 0603; Part Reference: RT115; PART_NUMBER: TMP-619; Manufacturer: Yageo; Manufacturer PN: RC0603JR-07120RL; Company Part Status: New; Temperature Coefficient: 100ppm/C; Rated Power: 0.1W, 1/10W; CLASS: DISCRETE
RT117 = R: RES SMD 10K OHM 1% 1/10W 0603; Part Reference: RT117; Manufacturer PN: MCR03ERTF1002; Manufacturer: Rohm Semiconductor; PART_NUMBER: TMP-380; Company Part Status: New; CLASS: DISCRETE; Rated Power: 0.1W, 1/10W; Temperature Coefficient: 100ppm/C
RT121 = R: CRGCQ 0603 180K 1%; Part Reference: RT121; Manufacturer PN: CRGCQ0603F180K; Manufacturer: TE Connectivity Passive Product; Company Part Status: New; CLASS: DISCRETE; Rated Power: 0.1W, 1/10W; Temperature Coefficient: 100ppm/C
RT122 = R: RES SMD 10K OHM 1% 1/10W 0603; Part Reference: RT122; Manufacturer PN: MCR03ERTF1002; Manufacturer: Rohm Semiconductor; PART_NUMBER: TMP-380; Company Part Status: New; CLASS: DISCRETE; Rated Power: 0.1W, 1/10W; Temperature Coefficient: 100ppm/C
RT123 = R: RES SMD 10K OHM 1% 1/10W 0603; Part Reference: RT123; Manufacturer PN: MCR03ERTF1002; Manufacturer: Rohm Semiconductor; PART_NUMBER: TMP-380; Company Part Status: New; CLASS: DISCRETE; Rated Power: 0.1W, 1/10W; Temperature Coefficient: 100ppm/C
RT124 = R: RES SMD 10K OHM 1% 1/10W 0603; Part Reference: RT124; PART_NUMBER: TMP-380; Manufacturer: Rohm Semiconductor; Manufacturer PN: MCR03ERTF1002; Company Part Status: New; Temperature Coefficient: 100ppm/C; Rated Power: 0.1W, 1/10W; CLASS: DISCRETE
RT125 = R: RES SMD 100K OHM 1% 1/10W 0603; Part Reference: RT125; PART_NUMBER: TMP-382; Manufacturer: Rohm Semiconductor; Manufacturer PN: MCR03ERTF1003; Company Part Status: New; Temperature Coefficient: 100ppm/C; Rated Power: 0.1W, 1/10W; CLASS: DISCRETE
RT126 = RES_Dup1: RES 45.3K OHM 1% 1/10W 0603; Part Reference: RT126; Manufacturer PN: RMCF0603FT45K3; Manufacturer: Stackpole Electronics Inc; Company Part Status: New; CLASS: DISCRETE; Rated Power: 0.1W, 1/10W; Temperature Coefficient: 100ppm/C
RT127 = R: RES SMD 120 OHM 5% 1/10W 0603; Part Reference: RT127; PART_NUMBER: TMP-619; Manufacturer: Yageo; Manufacturer PN: RC0603JR-07120RL; Company Part Status: New; Temperature Coefficient: 100ppm/C; Rated Power: 0.1W, 1/10W; CLASS: DISCRETE
RT128 = R: RES SMD 56K OHM 1% 1/10W 0603; Part Reference: RT128; PART_NUMBER: TMP-614; Manufacturer: Yageo; Manufacturer PN: RC0603FR-0756KL; Company Part Status: New; Temperature Coefficient: 100ppm/C; Rated Power: 0.1W, 1/10W; CLASS: DISCRETE
RT129 = RES_Dup1: RES SMD 165K OHM 0.1% 1/10W 0603; Part Reference: RT129; Manufacturer: Panasonic Electronic Components; Manufacturer PN: ERA-3AEB1653V; Company Part Status: New; Temperature Coefficient: 25ppm/C; Rated Power: 0.1W, 1/10W; CLASS: DISCRETE
RT130 = R: RES SMD 10K OHM 1% 1/10W 0603; Part Reference: RT130; Manufacturer PN: MCR03ERTF1002; Manufacturer: Rohm Semiconductor; PART_NUMBER: TMP-380; Company Part Status: New; CLASS: DISCRETE; Rated Power: 0.1W, 1/10W; Temperature Coefficient: 100ppm/C
RT131 = R: RES SMD 10K OHM 1% 1/10W 0603; Part Reference: RT131; Manufacturer PN: MCR03ERTF1002; Manufacturer: Rohm Semiconductor; PART_NUMBER: TMP-380; Company Part Status: New; CLASS: DISCRETE; Rated Power: 0.1W, 1/10W; Temperature Coefficient: 100ppm/C
RT132 = R: RES SMD 56K OHM 1% 1/10W 0603; Part Reference: RT132; PART_NUMBER: TMP-614; Manufacturer: Yageo; Manufacturer PN: RC0603FR-0756KL; Company Part Status: New; Temperature Coefficient: 100ppm/C; Rated Power: 0.1W, 1/10W; CLASS: DISCRETE
RT133 = R: RES SMD 100K OHM 1% 1/10W 0603; Part Reference: RT133; PART_NUMBER: TMP-382; Manufacturer: Rohm Semiconductor; Manufacturer PN: MCR03ERTF1003; Company Part Status: New; Temperature Coefficient: 100ppm/C; Rated Power: 0.1W, 1/10W; CLASS: DISCRETE
RT134 = RES_Dup1: RES 45.3K OHM 1% 1/10W 0603; Part Reference: RT134; Manufacturer PN: RMCF0603FT45K3; Manufacturer: Stackpole Electronics Inc; Company Part Status: New; CLASS: DISCRETE; Rated Power: 0.1W, 1/10W; Temperature Coefficient: 100ppm/C
RT135 = R: RES SMD 100K OHM 1% 1/10W 0603; Part Reference: RT135; PART_NUMBER: TMP-382; Manufacturer: Rohm Semiconductor; Manufacturer PN: MCR03ERTF1003; Company Part Status: New; Temperature Coefficient: 100ppm/C; Rated Power: 0.1W, 1/10W; CLASS: DISCRETE
RT136 = R: RES SMD 100K OHM 1% 1/10W 0603; Part Reference: RT136; Manufacturer PN: MCR03ERTF1003; Manufacturer: Rohm Semiconductor; PART_NUMBER: TMP-382; Company Part Status: New; CLASS: DISCRETE; Rated Power: 0.1W, 1/10W; Temperature Coefficient: 100ppm/C
RT137 = R: RES SMD 2.43K OHM 1% 1/8W 0805; Part Reference: RT137; Manufacturer PN: ERJ-6ENF2431V; Manufacturer: Panasonic Electronic Components; Company Part Status: New; CLASS: DISCRETE; Rated Power: 0.125W, 1/8W; Temperature Coefficient: 100ppm/C
RT138 = R: RES SMD 2.43K OHM 1% 1/8W 0805; Part Reference: RT138; Manufacturer PN: ERJ-6ENF2431V; Manufacturer: Panasonic Electronic Components; Company Part Status: New; CLASS: DISCRETE; Rated Power: 0.125W, 1/8W; Temperature Coefficient: 100ppm/C
RT139 = R: RES SMD 22K OHM 1% 1/10W 0603; Part Reference: RT139; PART_NUMBER: TMP-786; Manufacturer: Panasonic Electronic Components; Manufacturer PN: ERJ-3EKF2202V; Temperature Coefficient: 100ppm/C; Rated Power: 0.1W, 1/10W; CLASS: DISCRETE
RT140 = R: RES SMD 200K OHM 1% 1/10W 0603; Part Reference: RT140; Manufacturer: Panasonic Electronic Components; Manufacturer PN: ERJ-3EKF2003V; Company Part Status: New; Temperature Coefficient: 100ppm/C; Rated Power: 0.1W, 1/10W; CLASS: DISCRETE
RT141 = RES_Dup1: RES 0.01 OHM 1% 2W 2512; Part Reference: RT141; Manufacturer PN: PE2512FKE7W0R01L; Manufacturer: Yageo; Company Part Status: New; CLASS: DISCRETE; Temperature Coefficient: 50ppm/C
RT142 = R: RES SMD 100K OHM 1% 1/10W 0603; Part Reference: RT142; PART_NUMBER: TMP-382; Manufacturer: Rohm Semiconductor; Manufacturer PN: MCR03ERTF1003; Company Part Status: New; Temperature Coefficient: 100ppm/C; Rated Power: 0.1W, 1/10W; CLASS: DISCRETE
RT143 = R: RES SMD 2.7M OHM 5% 1/10W 0603; Part Reference: RT143; Manufacturer: Yageo; Manufacturer PN: RC0603JR-072M7L; Company Part Status: New; Temperature Coefficient: 100ppm/C; Rated Power: 0.1W, 1/10W; CLASS: DISCRETE
RT144 = R: RES SMD 2.7M OHM 5% 1/10W 0603; Part Reference: RT144; Manufacturer: Yageo; Manufacturer PN: RC0603JR-072M7L; Company Part Status: New; Temperature Coefficient: 100ppm/C; Rated Power: 0.1W, 1/10W; CLASS: DISCRETE
UB1 = REF3312AIDCKR - Vref_0: IC VREF SERIES 1.5V SOT-23-3; Part Reference: UB1; Manufacturer: Intersil; PART_NUMBER: TMP-150
UB2 = REF3312AIDCKR - Vref_0: IC VREF SERIES 3V SOT23-3; Part Reference: UB2; Manufacturer: Renesas Electronics America Inc.; Company Part Status: New
UT26 = LM7805: DC DC CONVERTER 5V 5W; Part Reference: UT26; Manufacturer: Recom Power; Company Part Status: New; PCB Footprint: TO-220V; CLASS: IC
UT27 = LM7805: DC DC CONVERTER 3.3V 3W; Part Reference: UT27; Manufacturer: Recom Power; Company Part Status: New; PCB Footprint: TO-220V; CLASS: IC; Rated Power: 3.3 W
UT28 = MOSFET_N_GSD: MOSFET N-CH 50V 0.2A SOT-23; Part Reference: UT28; Manufacturer: ON Semiconductor; Company Part Status: Released; Rated Power: 350mW; Polarity: N-Channel; CLASS: DISCRETE
UT29 = LT3581: IC REG MULTI CONFG ADJ 16MSOP; Part Reference: UT29; Manufacturer PN: LT3581EMSE#PBF; Manufacturer: Linear Technology/Analog Devices; Company Part Status: New; PACK_SHORT: (SW1,SW11,SW12),(SW2,SW21,SW22)
UT30 = MOSFET_N_GSD: MOSFET N-CH 50V 0.2A SOT-23; Part Reference: UT30; Manufacturer: ON Semiconductor; Company Part Status: Released; CLASS: DISCRETE; Polarity: N-Channel; Rated Power: 350mW
UT31 = LT3581: IC REG MULTI CONFG ADJ 16MSOP; Part Reference: UT31; Manufacturer PN: LT3581EMSE#PBF; Manufacturer: Linear Technology/Analog Devices; Company Part Status: New; PACK_SHORT: (SW1,SW11,SW12),(SW2,SW21,SW22)
UT32 = LTC4368: IC SURGE SUPPRESSION ADJ 10MSOP; Part Reference: UT32; Manufacturer: Linear Technology/Analog Devices; Company Part Status: New; Supply Voltage: 2.5 - 60 V

## Sheet Revision History.SchDoc: Controller
size 492 x 365 mm; OrgAddr3: USA; Page Create Date: March  8, 1995; OrgName: Wolfspeed; OrgAddr1: 535 W Research Center Blvd.; Page Number: 8; Page Size: A; Comment: DualBrandTitleBlock1; Page Count: 8; OrgAddr2: Fayetteville, AR, 72701; Page Name: Revision History; RevCode: V1.2; DsnPath: C:\Users\cnew\Downloads\xm3 controller v1r2-2022-03-14T15-49\xm3 controller v1r2.dsn; SchematicName: SCHEMATIC1; PageName: Revision History; PageSize: A; TopSchematic: True
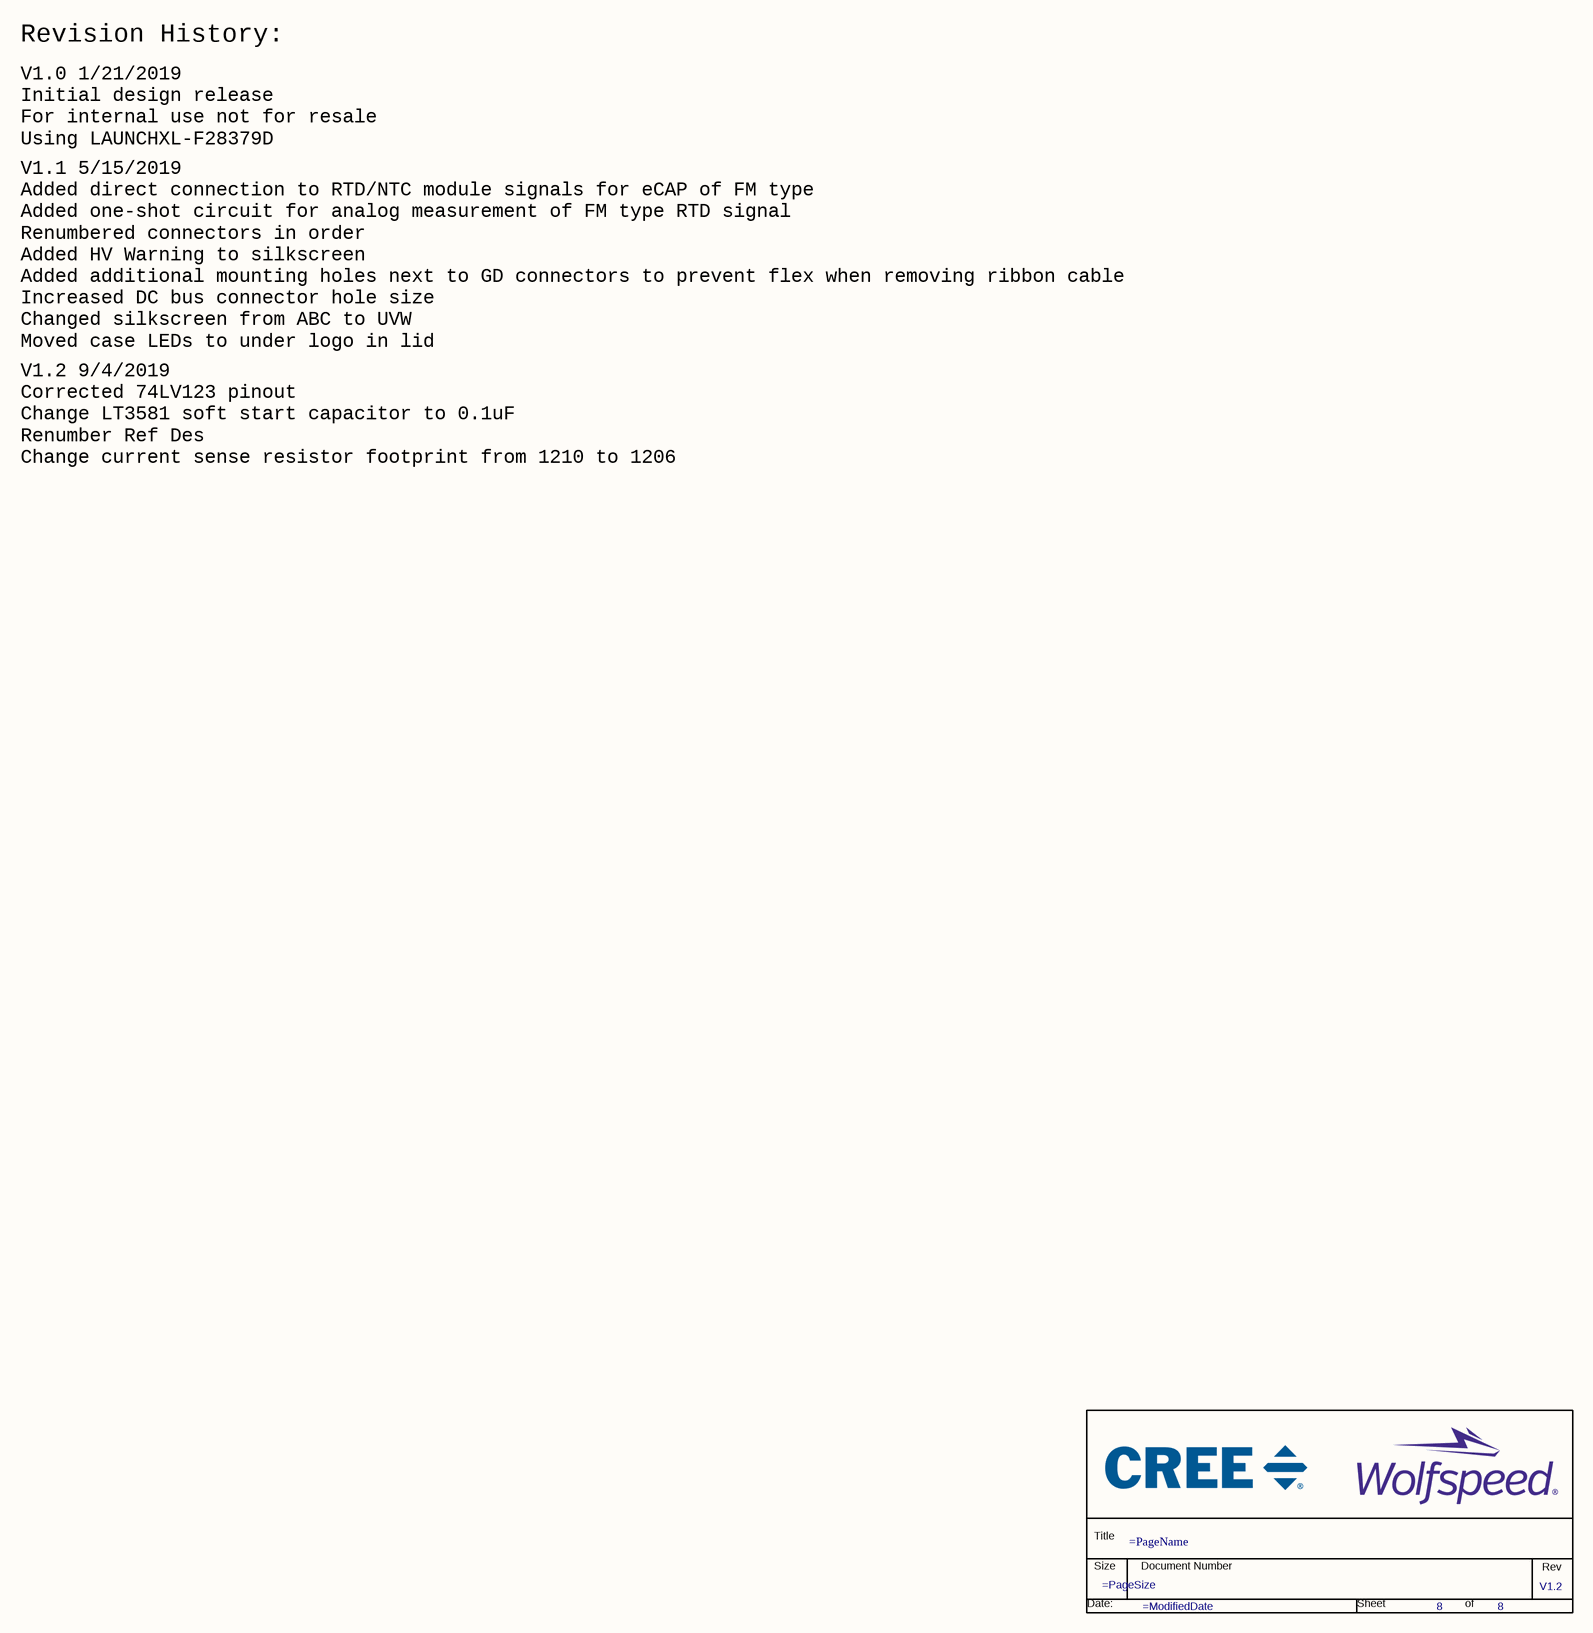
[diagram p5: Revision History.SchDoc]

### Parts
(Parts that share a designator on the sheet are numbered #1, #2 ... from top to bottom, then left to right.)
*#6  Page Count: 8  RevCode: V1.2  (hidden comment: DualBrandTitleBlock1)  (graphical)

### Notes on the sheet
- Revision History:
- V1.0 1/21/2019
  Initial design release
  For internal use not for resale
  Using LAUNCHXL-F28379D
- V1.1 5/15/2019
  Added direct connection to RTD/NTC module signals for eCAP of FM type
  Added one-shot circuit for analog measurement of FM type RTD signal
  Renumbered connectors in order
  Added HV Warning to silkscreen
  Added additional mounting holes next to GD connectors to prevent flex when removing ribbon cable
  Increased DC bus connector hole size
  Changed silkscreen from ABC to UVW
  Moved case LEDs to under logo in lid
- V1.2 9/4/2019
  Corrected 74LV123 pinout
  Change LT3581 soft start capacitor to 0.1uF
  Renumber Ref Des
  Change current sense resistor footprint from 1210 to 1206

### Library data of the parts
*#6 = DualBrandTitleBlock1: as *#4 on sheet LAUNCHPAD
